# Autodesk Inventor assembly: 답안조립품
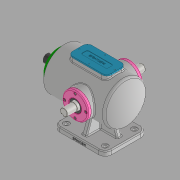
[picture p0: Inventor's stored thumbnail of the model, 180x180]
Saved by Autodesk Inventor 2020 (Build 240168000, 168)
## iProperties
Created: 2021-11
Part Number: 답안조립품
Document SubType Name: Assembly
Designer: Administrator
Author: Administrator
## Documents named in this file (14)
- C:\Users\Administrator\Desktop\711106V1030\답안조립품.iam
- C:\Users\Administrator\Desktop\711106V1030\본체.ipt
- C:\Users\Administrator\Desktop\711106V1030\베어링 6205.ipt
- 베어링 6205.ipt
- C:\Users\Administrator\Desktop\711106V1030\볼트 M4x0.7.ipt
- C:\Users\Administrator\Desktop\711106V1030\부시.ipt
- C:\Users\Administrator\Desktop\711106V1030\상부커버.ipt
- C:\Users\Administrator\Desktop\711106V1030\슬라이드 커버.ipt
- C:\Users\Administrator\Desktop\711106V1030\슬라이드.ipt
- C:\Users\Administrator\Desktop\711106V1030\오일실.ipt
- 오일실.ipt
- C:\Users\Administrator\Desktop\711106V1030\육각머리볼트 M4.ipt
- C:\Users\Administrator\Desktop\711106V1030\축 커버.ipt
- C:\Users\Administrator\Desktop\711106V1030\편심축.ipt
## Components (12 placed, 1 different names)
1. M4x0.7:1 — 각도:1
2. M4x0.7:4
3. M4x0.7:5
4. M4x0.7:6
5. M4x0.7:2 — 각도:2
6. M4x0.7:7
7. M4x0.7:8
8. M4x0.7:9
9. M4x0.7:3 — 각도:3
10. M4x0.7:10
11. M4x0.7:11
12. M4x0.7:12
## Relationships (3: Angle 3)
- 각도:1 [Angle]: M4x0.7:1
- 각도:2 [Angle]: M4x0.7:2
- 각도:3 [Angle]: M4x0.7:3
